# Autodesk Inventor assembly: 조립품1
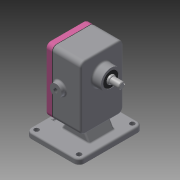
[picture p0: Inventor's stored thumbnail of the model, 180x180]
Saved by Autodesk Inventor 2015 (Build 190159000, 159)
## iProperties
Created: 2020-04
Part Number: 조립품1
Document SubType Name: Assembly
Designer: CAD-08
Author: CAD-08
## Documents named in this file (11)
- C:\Users\CAD-08\Desktop\700407V1038\조립품1.iam
- C:\Users\CAD-08\Desktop\700407V1038\Ű 6 x 6 x 18.ipt
- C:\Users\CAD-08\Desktop\700407V1038\개스킷.ipt
- C:\Users\CAD-08\Desktop\700407V1038\메인축.ipt
- C:\Users\CAD-08\Desktop\700407V1038\베어링부시.ipt
- C:\Users\CAD-08\Desktop\700407V1038\본체.ipt
- C:\Users\CAD-08\Desktop\700407V1038\볼트 M5.ipt
- C:\Users\CAD-08\Desktop\700407V1038\서브축.ipt
- C:\Users\CAD-08\Desktop\700407V1038\스퍼기어.ipt
- C:\Users\CAD-08\Desktop\700407V1038\오일 실 16 28 7.ipt
- C:\Users\CAD-08\Desktop\700407V1038\커버.ipt
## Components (3 placed, 2 different names)
1. Ű 6 x 6 x 18:1 — 각도:1, 각도:2
2. 개스킷:1
3. Ű 6 x 6 x 18:2 — 각도:3, 각도:4
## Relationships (4: Angle 4)
- 각도:1 [Angle]: Ű 6 x 6 x 18:1
- 각도:2 [Angle]: Ű 6 x 6 x 18:1
- 각도:3 [Angle]: Ű 6 x 6 x 18:2
- 각도:4 [Angle]: Ű 6 x 6 x 18:2
